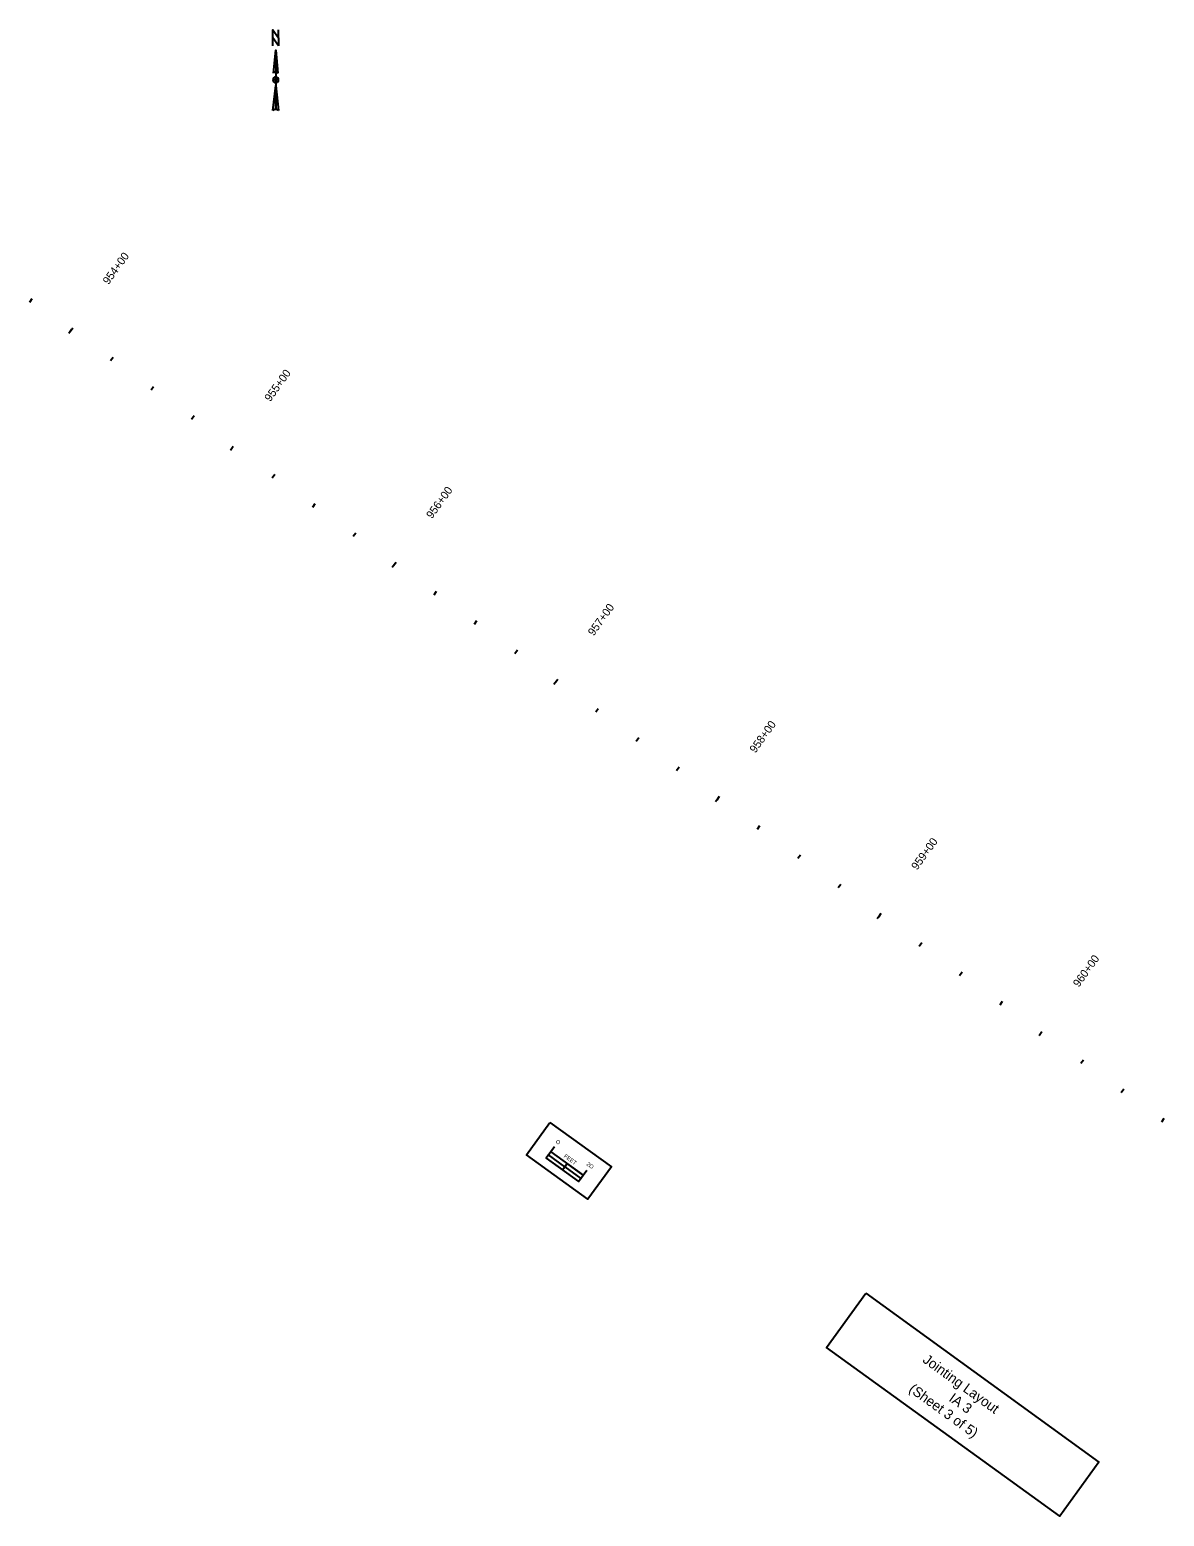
# Model space of a CAD drawing. Extents: x 14311466 to 14314811, y 8682098 to 8684603.
# Drawn here: x 14313148 to 14313716, y 8682797 to 8683542 of the extents above; entities that cross this region are included whole.
import ezdxf

# ---------------------------------------------------------------- set-up
doc = ezdxf.new("R2010")
doc.units = 0
for name, color, linetype in [('Cell', 7, 'Continuous'), ('SheetText', 7, 'Continuous'), ('TextAlignmentLrg', 7, 'Continuous'), ('TextAlignmentSml', 7, 'Continuous')]:
    doc.layers.add(name, color=color, linetype=linetype)

msp = doc.modelspace()

# ---------------------------------------------------------------- linework, layer by layer
at = {"layer": 'Cell'}
for p, q in [((14313270.96, 8683531.41), (14313272.1, 8683520)), ((14313270.96, 8683531.41), (14313270.96, 8683501.74)), ((14313269.82, 8683520), (14313269.82, 8683520)), ((14313269.86, 8683520.1), (14313270.08, 8683520.34)), ((14313269.53, 8683501.17), (14313270.96, 8683513.72)), ((14313270.96, 8683515.15), (14313270.96, 8683515.15))]:
    msp.add_line(p, q, dxfattribs=at)
for points in [[(14313272.39, 8683533.69), (14313269.53, 8683537.68), (14313269.53, 8683541.68), (14313272.39, 8683537.68)], [(14313566.48, 8682908.92), (14313683.32, 8682824.33), (14313663.65, 8682797.16), (14313546.81, 8682881.76)]]:
    msp.add_lwpolyline(points, close=True, dxfattribs=at)
for points in [[(14313269.53, 8683533.69), (14313269.53, 8683541.68), (14313272.39, 8683537.68), (14313272.39, 8683541.68)], [(14313269.82, 8683520), (14313270.96, 8683531.41), (14313270.96, 8683520.57)], [(14313270.96, 8683515.15), (14313270.96, 8683516.58), (14313269.53, 8683516.58)], [(14313272.39, 8683516.58), (14313270.96, 8683516.58), (14313270.96, 8683518)], [(14313270.96, 8683501.74), (14313270.96, 8683513.72), (14313272.39, 8683501.17)]]:
    msp.add_lwpolyline(points, dxfattribs=at)
for centre, radius, start, end in [((14313270.96, 8683516.58), 1.43, 90, 180), ((14313270.96, 8683516.58), 1.43, 180, 270), ((14313270.96, 8683519.14), 1.43, 90.02039, 143.12574), ((14313270.96, 8683519.14), 1.43, 36.84806, 90.02184), ((14313270.96, 8683516.58), 1.43, 0, 90), ((14313270.96, 8683516.58), 1.43, 270, 360), ((14313270.96, 8683499.68), 2.07, 89.98939, 133.61895), ((14313270.96, 8683499.68), 2.07, 46.40206, 90.00064)]:
    msp.add_arc(centre, radius, start, end, dxfattribs=at)
at = {"layer": 'SheetText'}
msp.add_line((14313414.54, 8682970.62), (14313416.88, 8682973.85), dxfattribs=at)
msp.add_line((14313414.54, 8682970.62), (14313416.88, 8682973.85), dxfattribs=at)
for points in [[(14313408.3, 8682994.39), (14313439.08, 8682972.11), (14313427.35, 8682955.91), (14313396.57, 8682978.19)], [(14313408.3, 8682994.39), (14313439.08, 8682972.11), (14313427.35, 8682955.91), (14313396.57, 8682978.19)], [(14313406.44, 8682976.48), (14313414.54, 8682970.62), (14313415.72, 8682972.25), (14313407.62, 8682978.11)], [(14313415.72, 8682972.25), (14313423.82, 8682966.38), (14313424.98, 8682967.99), (14313416.88, 8682973.85)]]:
    msp.add_lwpolyline(points, close=True, dxfattribs=at)
for points in [[(14313410.54, 8682982.15), (14313406.44, 8682976.48), (14313422.64, 8682964.75), (14313426.74, 8682970.42)], [(14313408.78, 8682979.72), (14313424.98, 8682967.99)]]:
    msp.add_lwpolyline(points, dxfattribs=at)
at = {"layer": 'TextAlignmentLrg'}
for p, q in [((14313168, 8683390.61), (14313169.28, 8683392.38)), ((14313249.71, 8683332.95), (14313248.28, 8683330.97)), ((14313329.99, 8683273.32), (14313331.27, 8683275.08)), ((14313410.99, 8683214.67), (14313412.27, 8683216.44)), ((14313491.99, 8683156.02), (14313493.27, 8683157.79)), ((14313572.99, 8683097.38), (14313574.27, 8683099.15)), ((14313654.7, 8683039.72), (14313653.27, 8683037.74))]:
    msp.add_line(p, q, dxfattribs=at)
at = {"layer": 'TextAlignmentSml'}
for p, q in [((14313147.75, 8683405.27), (14313149.03, 8683407.04)), ((14313168.72, 8683391.6), (14313167.28, 8683389.62)), ((14313188.25, 8683375.95), (14313189.53, 8683377.71)), ((14313208.5, 8683361.28), (14313209.78, 8683363.05)), ((14313228.75, 8683346.62), (14313230.03, 8683348.39)), ((14313249.71, 8683332.95), (14313248.28, 8683330.97)), ((14313269.25, 8683317.3), (14313270.53, 8683319.07)), ((14313289.5, 8683302.64), (14313290.78, 8683304.41)), ((14313309.74, 8683287.98), (14313311.03, 8683289.75)), ((14313330.71, 8683274.31), (14313329.28, 8683272.32)), ((14313350.24, 8683258.65), (14313351.52, 8683260.42)), ((14313370.49, 8683243.99), (14313371.77, 8683245.76)), ((14313390.74, 8683229.33), (14313392.02, 8683231.1)), ((14313411.71, 8683215.66), (14313410.27, 8683213.68)), ((14313431.24, 8683200.01), (14313432.52, 8683201.78)), ((14313451.49, 8683185.35), (14313452.77, 8683187.12)), ((14313471.74, 8683170.69), (14313473.02, 8683172.45)), ((14313492.71, 8683157.02), (14313491.27, 8683155.03)), ((14313512.24, 8683141.36), (14313513.52, 8683143.13)), ((14313532.49, 8683126.7), (14313533.77, 8683128.47)), ((14313552.74, 8683112.04), (14313554.02, 8683113.81)), ((14313573.71, 8683098.37), (14313572.27, 8683096.39)), ((14313593.24, 8683082.72), (14313594.52, 8683084.49)), ((14313613.49, 8683068.06), (14313614.77, 8683069.82)), ((14313633.74, 8683053.39), (14313635.02, 8683055.16)), ((14313654.7, 8683039.72), (14313653.27, 8683037.74)), ((14313674.24, 8683024.07), (14313675.52, 8683025.84)), ((14313694.48, 8683009.41), (14313695.77, 8683011.18)), ((14313714.73, 8682994.75), (14313716.02, 8682996.52))]:
    msp.add_line(p, q, dxfattribs=at)

# ---------------------------------------------------------------- texts
at = {"layer": 'Cell'}
for s, p in [('Jointing Layout', (14313594.6, 8682874.65)), ('(Sheet 3 of 5)', (14313587.65, 8682859.93)), ('IA 3', (14313607.74, 8682855.26))]:
    msp.add_text(s, height=5, rotation=324.09397, dxfattribs=at).set_placement(p)
at = {"layer": 'SheetText'}
for s, p in [('O', (14313410.92, 8682984.35)), ('FEET', (14313415.08, 8682977.14)), ('2O', (14313426.4, 8682973.14))]:
    msp.add_text(s, height=2, rotation=324.09397, dxfattribs=at).set_placement(p)
at = {"layer": 'TextAlignmentLrg'}
for s, p in [('955+00', (14313268.21, 8683355.09)), ('960+00', (14313673.2, 8683061.86))]:
    msp.add_text(s, height=4.008, rotation=54.09397, dxfattribs=at).set_placement(p)
at = {"layer": 'TextAlignmentSml'}
for s, p in [('954+00', (14313187.21, 8683413.73)), ('955+00', (14313268.21, 8683355.09)), ('956+00', (14313349.21, 8683296.44)), ('957+00', (14313430.21, 8683237.79)), ('958+00', (14313511.21, 8683179.15)), ('959+00', (14313592.2, 8683120.5)), ('960+00', (14313673.2, 8683061.86))]:
    msp.add_text(s, height=4.008, rotation=54.09397, dxfattribs=at).set_placement(p)

doc.saveas('drawing.dxf')
